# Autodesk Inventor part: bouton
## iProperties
Created: 2002-03
Part Number: bouton
Material: Par défaut
Document SubType Name: Modélisation
Designer: User
Control State: 0
Master: False
Checked Out: False
Shininess: 20.0
Length Units: 11269
Angle Units: 11279
Time Units: 11290
Mass Units: 11283
Length Display Precision: 3
Angle Display Precision: 2
Density: 0.0
Volumn: 0.0
Area: 0.0
PropertySet Name: Model Information
Author: User
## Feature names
1. Révolution1 [Revolution]
2. Extrusion1
3. Extrusion3
4. Extrusion4
5. Extrusion5
6. Extrusion6
7. Réseau circulaire1 [Circular Pattern]
8. Chanfrein1 [Chamfer]
9. Congé1 [Fillet]
